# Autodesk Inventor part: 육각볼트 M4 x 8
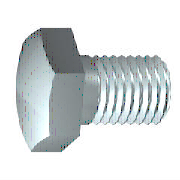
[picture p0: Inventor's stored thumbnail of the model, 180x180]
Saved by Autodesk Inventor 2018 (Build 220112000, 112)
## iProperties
Created: 2012-02
Part Number: 육각볼트 M4 x 8
Material: 강철, 연강
Description: 6각 머리 나사
Document SubType Name: Modeling
Standard: ISO 4017
Designer: mduedu
Standard Revision: Third edition 1999-08-15
Standards Organization: ISO
Language: ko-KR
Size Designation: M4 x 10
Categories: <MemberInstance><Categories><Category DisplayName="조임쇠" InternalName="e4da775c-781d-43d5-af7c-5136215cf5a6" Mnemonic="FSTN"><Category DisplayName="볼트" InternalN
Density: 7.86 g/cm^3
Appearance: 반광택
IsCustomPart: 0
Author: mduedu
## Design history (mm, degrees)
sketch "스케치1"
  geometry: L1 (0, 3.015)-(0, 2); L2 (1.75, 2)-(8, 2); L3 (8, 2)-(8, 0); L4 (8, 0)-(-0.4, 0); L5 (-2.08, 0)-(9.68, 0) reference; L6 (-0.4, 0)-(-0.4, 3.015); L7 (-0.4, 3.015)-(0, 3.015); L8 (1.75, 2)-(1.32, 2); L9 (1.32, 2)-(0, 2); L10 (0, -0.603)-(0, 3.618) reference
  constraints: 16 end point, 2 collinear, 2 perpendicular, 1 parallel
  dimensions: "d0" = 8 distance between parallel lines of L3 L1 (= NLG); "d1" = 6.25 distance from line of L2.start L3 (= GEL); "d2" = 4 diameter of L2 L4 (= GD); "d9" = 0.4001 distance between parallel lines of L6 L1 (computed from SD); "d10" = 6.03 diameter of L7 L4 (= SD2); "d13" = 0.42952 distance of L2.start L8.end (computed from GAL); "d14" = 4 diameter of L9 L4 (= BDM)
revolve "본체" sketch "스케치1" stored, may be unused: angle "d12" = 90 deg
sketch "스케치2"
  geometry: L1 (0, 4.041)-(3.5, 2.021); L2 (3.5, 2.021)-(3.5, -2.021); L3 (3.5, -2.021)-(0, -4.041); L4 (0, -4.041)-(-3.5, -2.021); L5 (-3.5, -2.021)-(-3.5, 2.021); L6 (-3.5, 2.021)-(0, 4.041); 2 further points
  constraints: 12 end point, 1 coincident, 1 vertical, 11 other
  dimensions: "d11" = 7 distance between parallel lines of L5 L2 (= SW)
extrude "머리" join sketch "스케치2" distance "d3" = 2.4 (= KOH - SD); taper "d4" = 0 deg
sketch "스케치4"
  geometry: L1 (-2.8, 3.5)-(-2.8, 4.041); L2 (-2.8, 4.041)-(-2.487, 4.041); L3 (-2.487, 4.041)-(-2.8, 3.5); L4 (-3.28, 0)-(0.08, 0) reference; L5 (-0.4, 4.041)-(-2.8, 4.041) reference; L6 (-2.8, 2.021)-(-2.8, 4.041) reference
  constraints: 6 end point, 2 collinear, 1 perpendicular, 1 vertical
  dimensions: "d5" = 30 deg angle of L3 L1 (= ANG1); "d19" = 7 diameter of L1.start L4 (= SW0)
revolve "모따기1" sketch "스케치4" stored, may be unused: angle "d21" = 90 deg
workplane "Work Plane1"
body "Solid1"
feature "스레드" dims "d15" = 6.25 (= GEL), "d16" = 0
chamfer "모따기2" distance "d6" = 0.42941 (= -0.5 x SPD + 0.5 x GD); stored, may be unused: second distance "d7" = 0.42952 (computed from GUL), angle "d55" = 45 deg
other parameters: "NLG" = 8 [user parameter; used in 1 equation term], "GD" = 4 (= NND) [user parameter; used in 2 equation terms], "BDM" = 4 (= NND) [user parameter; used in 1 equation term], "KOH" = 2.8 [user parameter; used in 1 equation term], "GEL" = 6.25 [user parameter; used in 2 equation terms], "SW" = 7 [user parameter; used in 2 equation terms], "SW0" = 7 (= SW) [user parameter; used in 1 equation term], "SPD" = 3.14117 (= NND - 1.2269 x PTC) [user parameter; used in 1 equation term], "SD2" = 6.03 [user parameter; used in 2 equation terms], "SD" = 0.4 [user parameter; used in 2 equation terms], "ANG1" = 30 deg [user parameter; used in 1 equation term], "GAL" = 0.42941 (= 0.61345 x PTC) [user parameter; used in 1 equation term], "GUL" = 0.42941 (= 0.61345 x PTC) [user parameter; used in 1 equation term], "d8" = 0, "RR" = 0.2 [user parameter], "d57" = 0, "d58" = 0, "TPU" = 14.28571 (computed from PTC) [user parameter], "GD1" = 3.14117 (= THREADDIA - 1.2269 x PTC) [user parameter], "THREADDIA" = 4 [user parameter; used in 1 equation term], "SDH" = 6.03 (= SD2) [user parameter], "SDHG" = 2.1 [user parameter], "TOA" = 30 deg [user parameter], "PTC" = 0.7 [user parameter; used in 5 equation terms], "NND" = 4 [user parameter; used in 3 equation terms], "E0" = 8.085 [user parameter]
